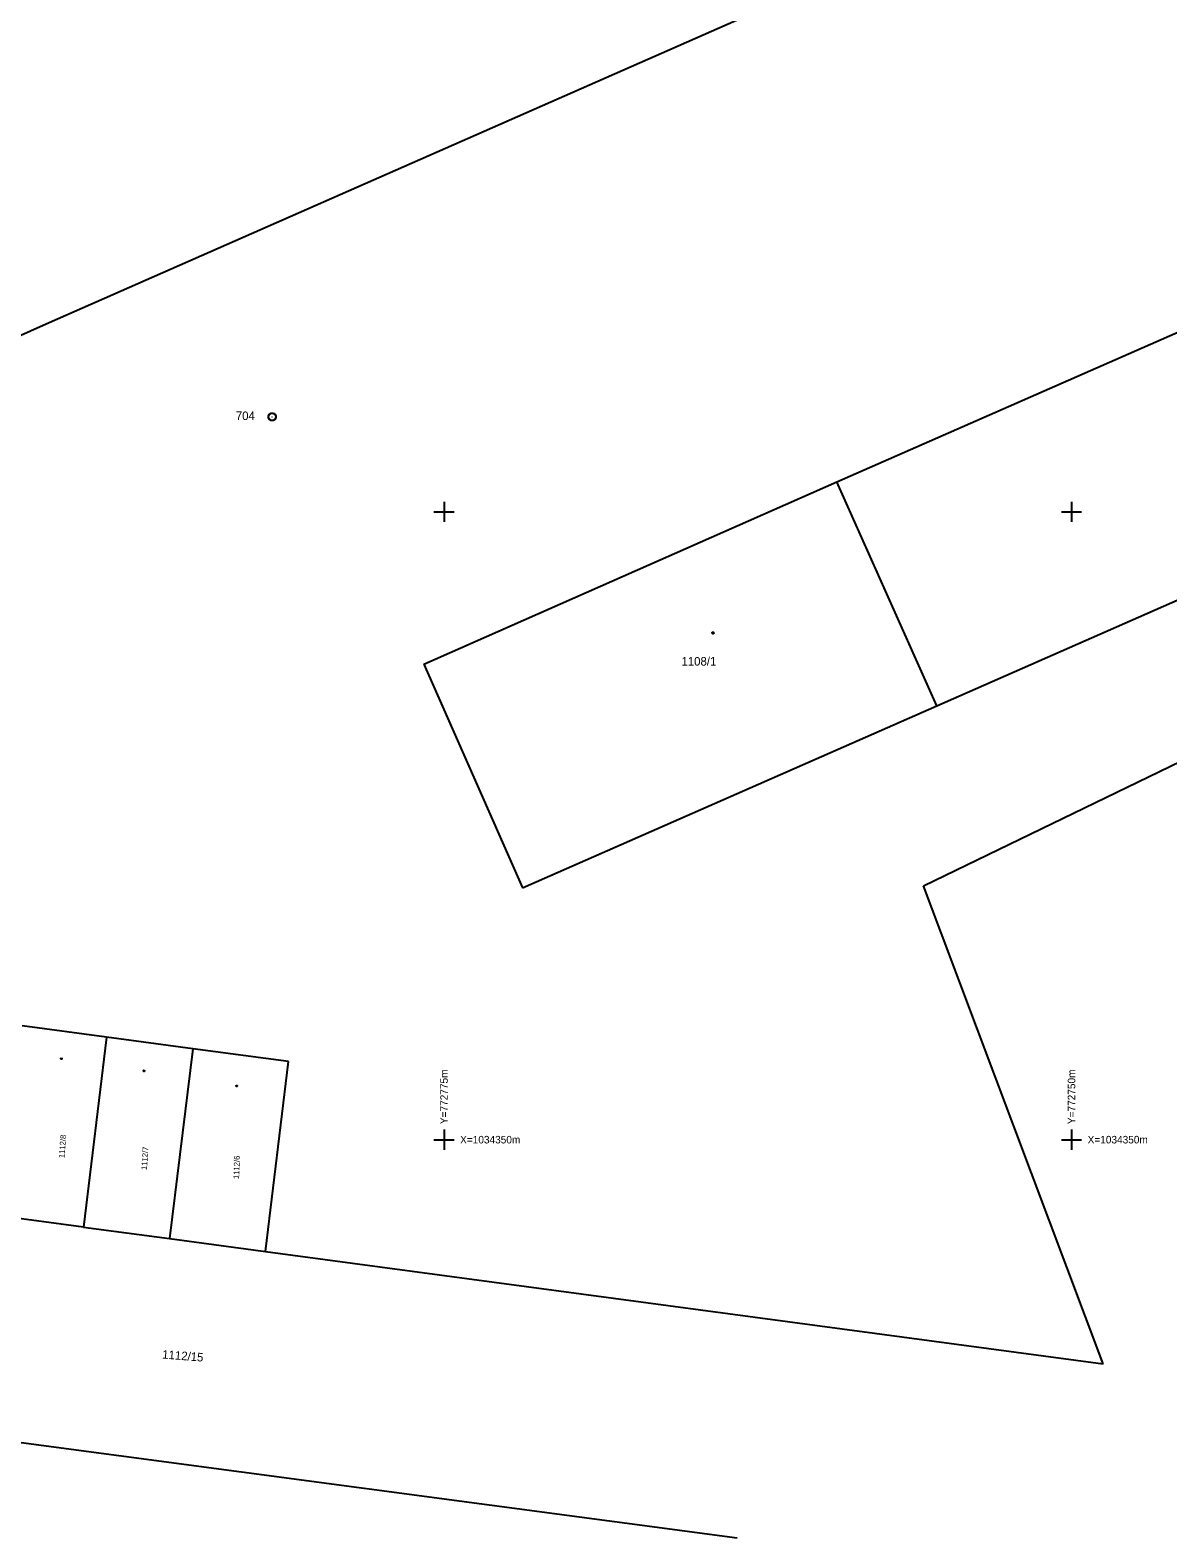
# Model space of a CAD drawing. Extents: x -772865 to -772533, y -1034366 to -1034132.
# Drawn here: x -772791.5 to -772746.2, y -1034365.9 to -1034305.8 of the extents above; entities that cross this region are included whole.
import ezdxf

# ---------------------------------------------------------------- set-up
doc = ezdxf.new("R2010")
doc.units = 0
for name, color, linetype in [('KM_hranice', 7, 'Continuous'), ('KM_kody_budov', 7, 'Continuous'), ('KM_mezni_znaky', 7, 'Continuous'), ('KM_parcelni_cisla', 7, 'Continuous'), ('KM_vnitrni_kresba', 7, 'Continuous'), ('souradnicova_sit', 7, 'Continuous')]:
    doc.layers.add(name, color=color, linetype=linetype)

msp = doc.modelspace()

# ---------------------------------------------------------------- linework, layer by layer
at = {"layer": 'KM_hranice'}
for p, q in [((-772736.19, -1034293.48), (-772790.73, -1034317.48)), ((-772759.35, -1034323.81), (-772742.88, -1034316.57)), ((-772790.73, -1034317.48), (-772819.67, -1034330.22)), ((-772775.81, -1034331.06), (-772759.35, -1034323.81)), ((-772755.37, -1034332.72), (-772738.87, -1034325.47)), ((-772775.81, -1034331.06), (-772771.87, -1034339.97)), ((-772755.9, -1034339.89), (-772737, -1034330.73)), ((-772771.87, -1034339.97), (-772755.37, -1034332.72)), ((-772748.74, -1034358.92), (-772755.9, -1034339.89)), ((-772788.44, -1034345.92), (-772791.81, -1034345.47)), ((-772788.44, -1034345.92), (-772789.36, -1034353.48)), ((-772785.01, -1034346.38), (-772788.44, -1034345.92)), ((-772785.01, -1034346.38), (-772785.93, -1034353.94)), ((-772781.2, -1034346.89), (-772785.01, -1034346.38)), ((-772782.11, -1034354.45), (-772781.2, -1034346.89)), ((-772789.36, -1034353.48), (-772792.73, -1034353.03)), ((-772789.36, -1034353.48), (-772785.93, -1034353.94)), ((-772785.93, -1034353.94), (-772782.11, -1034354.45)), ((-772782.11, -1034354.45), (-772748.74, -1034358.92)), ((-772824.45, -1034357.71), (-772763.317, -1034365.855))]:
    msp.add_line(p, q, dxfattribs=at)
at = {"layer": 'KM_kody_budov'}
for points in [[(-772764.29, -1034329.786), (-772764.27, -1034329.79), (-772764.26, -1034329.808), (-772764.256, -1034329.82), (-772764.26, -1034329.838), (-772764.276, -1034329.852), (-772764.29, -1034329.854), (-772764.308, -1034329.848), (-772764.32, -1034329.836), (-772764.324, -1034329.82), (-772764.32, -1034329.802), (-772764.304, -1034329.788)], [(-772790.24, -1034346.747), (-772790.227, -1034346.75), (-772790.22, -1034346.762), (-772790.217, -1034346.77), (-772790.22, -1034346.782), (-772790.231, -1034346.791), (-772790.24, -1034346.793), (-772790.252, -1034346.789), (-772790.26, -1034346.781), (-772790.263, -1034346.77), (-772790.26, -1034346.758), (-772790.249, -1034346.749)], [(-772786.95, -1034347.237), (-772786.937, -1034347.24), (-772786.93, -1034347.252), (-772786.927, -1034347.26), (-772786.93, -1034347.272), (-772786.941, -1034347.281), (-772786.95, -1034347.283), (-772786.962, -1034347.279), (-772786.97, -1034347.271), (-772786.973, -1034347.26), (-772786.97, -1034347.248), (-772786.959, -1034347.239)], [(-772783.26, -1034347.837), (-772783.247, -1034347.84), (-772783.24, -1034347.852), (-772783.237, -1034347.86), (-772783.24, -1034347.872), (-772783.251, -1034347.881), (-772783.26, -1034347.883), (-772783.272, -1034347.879), (-772783.28, -1034347.871), (-772783.283, -1034347.86), (-772783.28, -1034347.848), (-772783.269, -1034347.839)]]:
    msp.add_lwpolyline(points, close=True, dxfattribs=at)
at = {"layer": 'KM_mezni_znaky'}
msp.add_line((-772781.86, -1034321.22), (-772781.84, -1034321.22), dxfattribs=at)
msp.add_lwpolyline([(-772781.812, -1034321.076), (-772781.744, -1034321.114), (-772781.706, -1034321.182), (-772781.706, -1034321.26), (-772781.744, -1034321.328), (-772781.812, -1034321.366), (-772781.89, -1034321.366), (-772781.958, -1034321.328), (-772781.996, -1034321.26), (-772781.996, -1034321.182), (-772781.958, -1034321.114), (-772781.89, -1034321.076)], close=True, dxfattribs=at)
at = {"layer": 'KM_vnitrni_kresba'}
msp.add_line((-772755.37, -1034332.72), (-772759.35, -1034323.81), dxfattribs=at)
at = {"layer": 'souradnicova_sit'}
for p, q in [((-772775, -1034324.6), (-772775, -1034325.4)), ((-772750, -1034324.6), (-772750, -1034325.4)), ((-772775.4, -1034325), (-772774.6, -1034325)), ((-772750.4, -1034325), (-772749.6, -1034325)), ((-772775, -1034349.6), (-772775, -1034350.4)), ((-772750, -1034349.6), (-772750, -1034350.4)), ((-772775.4, -1034350), (-772774.6, -1034350)), ((-772750.4, -1034350), (-772749.6, -1034350))]:
    msp.add_line(p, q, dxfattribs=at)

# ---------------------------------------------------------------- texts
at = {"layer": 'KM_mezni_znaky'}
msp.add_text('704', height=0.34, dxfattribs=at).set_placement((-772783.294, -1034321.344))
at = {"layer": 'KM_parcelni_cisla'}
msp.add_text('1108/1', height=0.34, dxfattribs=at).set_placement((-772765.542, -1034331.122))
for s, height, rotation, p in [('1112/8', 0.228, 85.5426, (-772790.123, -1034350.744)), ('1112/7', 0.228, 86.11556, (-772786.838, -1034351.216)), ('1112/6', 0.228, 87.94902, (-772783.165, -1034351.572)), ('1112/15', 0.34, 355.52031, (-772786.237, -1034358.712))]:
    msp.add_text(s, height=height, rotation=rotation, dxfattribs=at).set_placement(p)
at = {"layer": 'souradnicova_sit'}
for s, p in [('Y=772775m', (-772774.85, -1034349.381)), ('Y=772750m', (-772749.85, -1034349.381))]:
    msp.add_text(s, height=0.3, rotation=90.01167, dxfattribs=at).set_placement(p)
for p in [(-772774.358, -1034350.15), (-772749.358, -1034350.15)]:
    msp.add_text('X=1034350m', height=0.3, dxfattribs=at).set_placement(p)

doc.saveas('drawing.dxf')
